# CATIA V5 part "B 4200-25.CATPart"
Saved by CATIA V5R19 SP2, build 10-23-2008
Part number: B 4200-25
Bounding box of the stored display mesh (mm): x -47.487 to 47.487, y -47.487 to 47.487, z 0 to 170
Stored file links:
  C:\Users\Bora\Desktop\3D Katı model\B serisi\B 4200\B 4200-25.CATPart
  C:\Program Files\Dassault Systemes\B19\intel_a\reffiles\standard\MetricThickPitch.txt
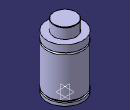
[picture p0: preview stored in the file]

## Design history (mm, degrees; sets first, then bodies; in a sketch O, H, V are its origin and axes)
Body1 (main body)
  Sketch1 on yz-plane, origin (0, 0, 0), H (0, 1, 0), V (0, 0, 1)
    point P1 (47.5, 123.5)
    point P2 (47.5, 118.5)
    point P3 (47.5, 123.5)
    point P6 (47.5, 118.5)
    point P9 (30, 169)
    point P11 (30, 169)
    arc A1 centre (47.5, 121) radius 2.5 from (47.5, 123.5) to (47.5, 118.5) ccw
    line L1 (47.5, 123.5) -> (47.5, 142)
    line L2 (47.5, 13) -> (47.5, 118.5)
    line L3 (43.5, 13) -> (43.5, 8)
    arc A2 centre (29, 169) radius 1 from (30, 169) to (29, 170) ccw
    line L4 (30, 169) -> (30, 142)
    line L5 (47.5, 0) -> (47.5, 8)
    line L6 (29, 170) -> (0, 170)
    point P15 (0, 170)
    line L7 (30, 142) -> (47.5, 142)
    line L8 (0, 0) -> (47.5, 0)
    line L9 (43.5, 13) -> (47.5, 13)
    line L10 (43.5, 8) -> (47.5, 8)
    coincidence: P15 V, P1 P3, P2 P6, P9 P11
    tangency: L6 A2
    horizontal: L7 H, L8 H, L9 H, L10 H
  Shaft1: profile Sketch1, axis Sketch1.V, angle 360
  Sketch2 on face of Shaft1 from Sketch1.L8, origin (0, 0, 0), H (1, 0, 0), V (0, -1, 0)
    point P1 (30, 0)
    distance P1 V = 30
  Hole1: placed by Sketch2, at (30, 0, 0) direction (0, 0, 1), diameter 6.647, depth 13, threaded "M8", thread diameter 8, thread depth 13, pitch 1.25
  CircPattern1: of Hole1, instances 4, angular step 90, axis from xy-plane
